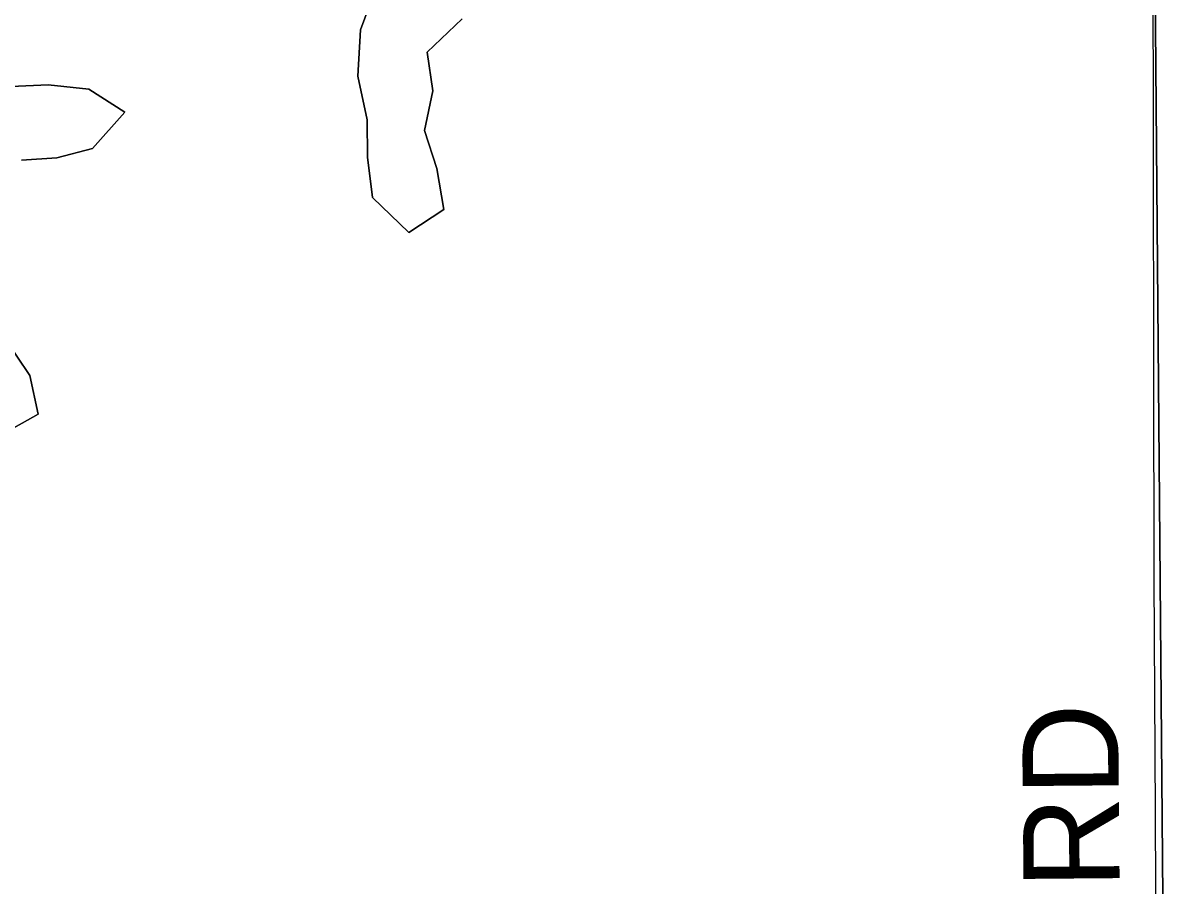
# Model space of a CAD drawing. Extents: x 0 to 34, y 0 to 22.
# Drawn here: x 3.775 to 4.456, y 15.535 to 16.045 of the extents above; entities that cross this region are included whole.
import ezdxf

# ---------------------------------------------------------------- set-up
doc = ezdxf.new("R2010")
doc.units = 0
for name, color, linetype in [('GM_X_Major_Lake', 7, 'Continuous'), ('GM_X_Major_River', 7, 'Continuous'), ('GM_X_Township', 7, 'Continuous'), ('GM_X_Township_Road', 7, 'Continuous'), ('GM_X_Township_Road_Text', 7, 'Continuous')]:
    doc.layers.add(name, color=color, linetype=linetype)

msp = doc.modelspace()

# ---------------------------------------------------------------- linework, layer by layer
at = {"layer": 'GM_X_Major_Lake'}
for points in [[(3.98254, 16.06337), (3.97409, 16.04084), (3.97252, 16.01346), (3.97813, 15.98769), (3.97839, 15.96565), (3.98132, 15.94174), (4.00278, 15.92112), (4.02346, 15.93468), (4.01938, 15.95896), (4.01192, 15.98128), (4.01695, 16.00491), (4.01365, 16.02767), (4.03425, 16.04731)], [(3.77384, 15.96379), (3.79465, 15.9652), (3.8158, 15.97079), (3.83487, 15.99231), (3.8135, 16.00572), (3.7896, 16.00846), (3.76764, 16.00742)], [(3.76286, 15.80214), (3.78355, 15.8138), (3.77874, 15.83654), (3.76332, 15.85953)]]:
    msp.add_lwpolyline(points, dxfattribs=at)
at = {"layer": 'GM_X_Major_River'}
for points in [[(4.03425, 16.04731), (4.01365, 16.02767), (4.01695, 16.00491), (4.01192, 15.98128), (4.01938, 15.95896), (4.02346, 15.93468), (4.00278, 15.92112), (3.98132, 15.94174), (3.97839, 15.96565), (3.97813, 15.98769), (3.97252, 16.01346), (3.97409, 16.04084), (3.98254, 16.06337)], [(3.76764, 16.00742), (3.7896, 16.00846), (3.8135, 16.00572), (3.83487, 15.99231), (3.8158, 15.97079), (3.79465, 15.9652), (3.77384, 15.96379)], [(3.76332, 15.85953), (3.77874, 15.83654), (3.78355, 15.8138), (3.76286, 15.80214)]]:
    msp.add_lwpolyline(points, dxfattribs=at)
at = {"layer": 'GM_X_Township'}
for points in [[(4.44923, 14.33849), (4.45435, 14.82679), (4.43778, 16.79078), (4.43381, 17.58349)], [(4.43381, 17.58349), (4.43778, 16.79078), (4.45435, 14.82679), (4.44923, 14.33849)]]:
    msp.add_lwpolyline(points, dxfattribs=at)
at = {"layer": 'GM_X_Township_Road'}
msp.add_lwpolyline([(4.4562, 14.82757), (4.45427, 14.83286), (4.45329, 14.83947), (4.45149, 14.98828), (4.44992, 15.09467), (4.44835, 15.16806), (4.44812, 15.2446), (4.44723, 15.35503), (4.44431, 15.53257), (4.44408, 15.57858), (4.44341, 15.71684), (4.44268, 16.09204)], dxfattribs=at)

# ---------------------------------------------------------------- texts
at = {"layer": 'GM_X_Township_Road_Text'}
msp.add_text('RD', height=0.056818, rotation=90.4939, dxfattribs=at).set_placement((4.42294, 15.5333))

doc.saveas('drawing.dxf')
